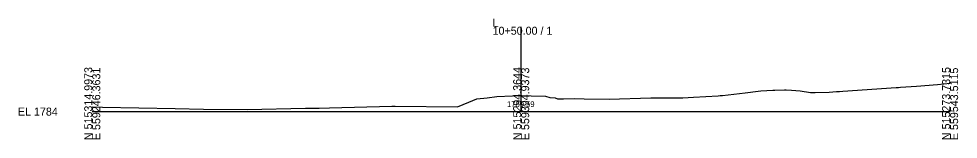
# Model space of a CAD drawing. Extents: x -26 to 1303, y -10 to 9545.
# Drawn here: x -25.7 to 302.8, y 990.3 to 1032.5 of the extents above; entities that cross this region are included whole.
import ezdxf

# ---------------------------------------------------------------- set-up
doc = ezdxf.new("R2010")
doc.units = 0
for name, color, linetype in [('Exist Cross Section Cell', 7, 'Continuous'), ('Exist XS Center Line Elevation Label', 7, 'Continuous'), ('Exist XS Ground Line', 7, 'Continuous')]:
    doc.layers.add(name, color=color, linetype=linetype)

msp = doc.modelspace()

# ---------------------------------------------------------------- linework, layer by layer
at = {"layer": 'Exist Cross Section Cell'}
for p, q in [((150, 1000), (150, 1029.73)), ((0, 1000), (150, 1000)), ((150, 1000), (300, 1000))]:
    msp.add_line(p, q, dxfattribs=at)
at = {"layer": 'Exist XS Ground Line'}
for p, q in [((282.62, 1008.51), (288.26, 1008.96)), ((288.26, 1008.96), (295.56, 1009.54)), ((295.56, 1009.54), (300, 1009.91)), ((141.54, 1005.27), (146.91, 1005.47)), ((146.91, 1005.47), (150.25, 1005.6)), ((150.25, 1005.6), (153.47, 1005.52)), ((153.47, 1005.52), (158.49, 1005.41)), ((158.49, 1005.41), (159.97, 1004.92)), ((210.26, 1005.07), (218.85, 1005.46)), ((218.85, 1005.46), (219.62, 1005.58)), ((219.62, 1005.58), (220.44, 1005.67)), ((220.44, 1005.67), (228.28, 1006.52)), ((228.28, 1006.52), (232.83, 1007.18)), ((232.83, 1007.18), (233.79, 1007.28)), ((233.79, 1007.28), (238.05, 1007.48)), ((238.05, 1007.48), (238.76, 1007.52)), ((238.76, 1007.52), (242.09, 1007.64)), ((242.09, 1007.64), (242.66, 1007.64)), ((242.66, 1007.64), (244.5, 1007.51)), ((244.5, 1007.51), (247.58, 1007.24)), ((247.58, 1007.24), (251.24, 1006.7)), ((251.24, 1006.7), (252.87, 1006.68)), ((252.87, 1006.68), (257.74, 1006.86)), ((257.74, 1006.86), (260.33, 1007.03)), ((260.33, 1007.03), (261.29, 1007.07)), ((261.29, 1007.07), (262.53, 1007.14)), ((262.53, 1007.14), (281.16, 1008.39)), ((281.16, 1008.39), (281.49, 1008.41)), ((281.49, 1008.41), (282.01, 1008.45)), ((282.01, 1008.45), (282.62, 1008.51)), ((127.78, 1001.7), (131.65, 1003.34)), ((131.65, 1003.34), (134.55, 1004.43)), ((134.55, 1004.43), (138.05, 1004.79)), ((138.05, 1004.79), (141.54, 1005.27)), ((159.97, 1004.92), (161.85, 1004.78)), ((161.85, 1004.78), (162.75, 1004.52)), ((162.75, 1004.52), (163.44, 1004.43)), ((163.44, 1004.43), (164.82, 1004.49)), ((164.82, 1004.49), (168.71, 1004.61)), ((168.71, 1004.61), (172.08, 1004.52)), ((172.08, 1004.52), (180.74, 1004.33)), ((180.74, 1004.33), (195.29, 1004.86)), ((195.29, 1004.86), (206.52, 1004.82)), ((206.52, 1004.82), (210.26, 1005.07)), ((0, 1001.63), (3.62, 1001.59)), ((3.62, 1001.59), (16.34, 1001.34)), ((16.34, 1001.34), (28.97, 1001.13)), ((28.97, 1001.13), (38.9, 1000.88)), ((38.9, 1000.88), (54.16, 1000.75)), ((54.16, 1000.75), (74.61, 1001.14)), ((74.61, 1001.14), (79.39, 1001.23)), ((79.39, 1001.23), (83.01, 1001.27)), ((83.01, 1001.27), (104.72, 1001.85)), ((104.72, 1001.85), (105.93, 1001.85)), ((105.93, 1001.85), (127.78, 1001.7))]:
    msp.add_line(p, q, dxfattribs=at)

# ---------------------------------------------------------------- texts
at = {"layer": 'Exist Cross Section Cell'}
for s, p in [('L', (140, 1029.73)), ('10+50.00 / 1', (140, 1026.93)), ('EL 1784', (-26, 998.6))]:
    msp.add_text(s, height=2.8, dxfattribs=at).set_placement(p)
for s, p in [('N 515314.9973', (0, 990)), ('E 559246.3631', (2.8, 990)), ('N 515294.3644', (150, 990)), ('E 559394.9373', (152.8, 990)), ('N 515273.7315', (300, 990)), ('E 559543.5115', (302.8, 990))]:
    msp.add_text(s, height=2.8, rotation=90, dxfattribs=at).set_placement(p)
at = {"layer": 'Exist XS Center Line Elevation Label'}
msp.add_text('1789.59', height=2, dxfattribs=at).set_placement((145.02, 1001.59))

doc.saveas('drawing.dxf')
